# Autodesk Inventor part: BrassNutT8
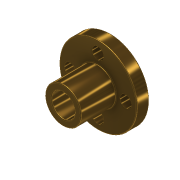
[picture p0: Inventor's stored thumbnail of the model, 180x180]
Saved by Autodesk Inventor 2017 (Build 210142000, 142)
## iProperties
Created: 2018-08
Part Number: BrassNutT8
Material: Brass
Document SubType Name: Modeling
Designer: JK
Density: 8.49 g/cm^3
Appearance: Brass - Polished
Author: JK
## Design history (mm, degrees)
sketch "Sketch1"
  geometry: C1 r 5.2 at (0, 0); C2 r 3.35 at (0, 0); 1 further point
  constraints: 2 centre point, 2 coincident
  dimensions: "d0" = 10.4 diameter of C1; "d1" = 6.7 diameter of C2
extrude "Extrusion1" new body sketch "Sketch1" distance "d2" = 15.6; taper "d3" = 0 deg
sketch "Sketch2"
  geometry: C1 r 11.2 at (0, 0); C2 r 5.2 at (0, 0); C3 r 1.7 at (-8, 0); C4 r 1.7 at (0, 8); C5 r 1.7 at (8, 0); C6 r 1.7 at (0, -8); 1 further point
  constraints: 6 centre point, 3 equal radius, 2 coincident
  dimensions: "d4" = 3.4 diameter of C3; "d5" = 22.4 diameter of C1; "d6" = 10.4 diameter of C2; "d7" = 8 distance of C3.centre point (0, 0); "d13" = 8 distance of point (0, 0) C6.centre; "d14" = 8 distance of point (0, 0) C4.centre; "d15" = 8 distance of point (0, 0) C5.centre
extrude "Extrusion4" join sketch "Sketch2" distance "d16" = 5.5; taper "d17" = 0 deg
workplane "Work Plane1"
sketch "Sketch3"
  geometry: C1 r 28.027 at (0, 0); C2 r 5.3 at (0, 0); 1 further point
  constraints: 2 centre point, 1 coincident
  dimensions: "d10" = 10.6 diameter of C2
extrude "Extrusion3" cut sketch "Sketch3" distance "d11" = 1.9; taper "d12" = 0 deg
fillet "Fillet1" dims "d18" = 0.25
body "Solid1"
